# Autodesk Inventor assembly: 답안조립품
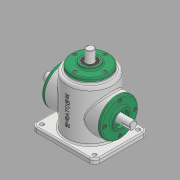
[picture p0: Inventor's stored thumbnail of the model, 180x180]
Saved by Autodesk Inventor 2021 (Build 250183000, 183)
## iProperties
Created: 2021-02
Part Number: 답안조립품
Document SubType Name: Assembly
Designer: 201-25
Author: 201-25
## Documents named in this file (16)
- C:\Users\201-25\Desktop\710214V1005\답안조립품.iam
- C:\Users\201-25\Desktop\710214V1005\본체.ipt
- C:\Users\201-25\Desktop\710214V1005\커버.ipt
- C:\Users\201-25\Desktop\710214V1005\베어링 6203.ipt
- C:\Users\201-25\Desktop\710214V1005\오일 실.ipt
- 오일 실.ipt
- C:\Users\201-25\Desktop\710214V1005\메인 축.ipt
- 메인 축.ipt
- C:\Users\201-25\Desktop\710214V1005\키 5x5.ipt
- C:\Users\201-25\Desktop\710214V1005\메인 베벨기어.ipt
- C:\Users\201-25\Desktop\710214V1005\서브 축.ipt
- 서브 축.ipt
- C:\Users\201-25\Desktop\710214V1005\키 4x4.ipt
- C:\Users\201-25\Desktop\710214V1005\서브 베벨기어.ipt
- C:\Users\201-25\Desktop\710214V1005\볼트 M4.ipt
- 볼트 M4.ipt
